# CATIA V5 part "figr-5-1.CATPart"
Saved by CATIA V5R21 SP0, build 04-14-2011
Part number: Part1
Bounding box of the stored display mesh (mm): x -23 to 23, y -104 to 104, z 0 to 68
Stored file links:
  D:\CATIA V5R21 E-RESOURCES\CATIA-V5R21\catia-v5r21-prt\c05-catia-v5r20-prt\catia-v5r21-figr-5-1.CATPart
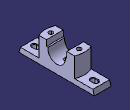
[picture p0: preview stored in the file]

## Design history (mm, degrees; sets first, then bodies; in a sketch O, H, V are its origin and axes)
Sketch1 on yz-plane, origin (0, 0, 0), H (0, 1, 0), V (0, 0, 1)
  line L1 (0, 0) -> (104, 0)
  point P1 (104, 0)
  line L2 (104, 0) -> (100, 14)
  point P2 (100, 14)
  line L3 (100, 14) -> (54, 14)
  point P3 (54, 14)
  line L4 (54, 14) -> (54, 68)
  point P4 (54, 68)
  line L5 (54, 68) -> (28, 68)
  point P5 (28, 68)
  line L6 (28, 68) -> (28, 52)
  point P6 (28, 52)
  line L7 (28, 52) -> (23.6643, 52)
  axis line L8 (0, 0) -> (0, 150)
  point P8 (0, 0)
  construction line L9 through (0, 0) direction (-1, 0)
  construction line L10 through (0, 0) direction (0, 1)
  point P13 (-104, 0)
  point P14 (-100, 14)
  point P15 (-54, 14)
  point P16 (-54, 68)
  point P17 (-28, 68)
  point P18 (-28, 52)
  line L11 (0, 0) -> (-104, 0)
  line L12 (-104, 0) -> (-100, 14)
  line L13 (-100, 14) -> (-54, 14)
  line L14 (-54, 14) -> (-54, 68)
  line L15 (-54, 68) -> (-28, 68)
  line L16 (-28, 68) -> (-28, 52)
  line L17 (-28, 52) -> (-23.6643, 52)
  arc A1 centre (0, 48) radius 24 from (-23.6643, 52) to (23.6643, 52) ccw
  point P19 (0, 48)
  point P20 (13.2665, 68)
  distance P1 P13 = 208
  length L2 V = 14
  length L2 H = 4
  distance L4 L14 = 108
  distance L16 L6 = 56
  distance L1 L5 = 68
  length L6 = 16
  distance P19 L7 = 4
  radius A1 = 24
  horizontal: L1 H, L3 H, L5 H, L7 H
  vertical: L4 V, L6 V, L8 V
  symmetry: O P8 L8, H L9 L8, V L10 L8, P1 P13 L8, P2 P14 L8, P3 P15 L8, P4 P16 L8, P5 P17 L8, P6 P18 L8, L1 L11 L8, L2 L12 L8, L3 L13 L8, L4 L14 L8, L5 L15 L8, L6 L16 L8, L7 L17 L8
  coincidence: P19 L8, A1 P20, P20 L5, O P8
Pad1: profile Sketch1, direction (1, 0, 0), length 23, mirrored extent
Body1 (main body)
  Sketch2 on face of Pad1, origin (0, 0, 68), H (1, 0, 0), V (0, 1, 0)
    arc A1 centre (0, 0) radius 54 from (-23, 48.8569) to (23, 48.8569) cw
    point P1 (0, 0)
    point P2 (-23, 48.8569)
    point P3 (23, 48.8569)
    reference projected line E1 (23, 54) -> (23, 28) from edge [face of Pad1 | face of Pad1]
    reference projected line E2 (-23, 54) -> (-23, 28) from edge [face of Pad1 | face of Pad1]
    reference projected line E3 (-23, 54) -> (23, 54) from edge [face of Pad1 | face of Pad1]
    axis line L1 (-38.3733, 0) -> (57.2772, 0)
    point P4 (-38.3733, 0)
    point P6 (-23, -48.8569)
    point P7 (23, -48.8569)
    arc A2 centre (0, 0) radius 54 from (-23, -48.8569) to (23, -48.8569) ccw
    line L2 (-23, 48.8569) -> (-23, -48.8569)
    point P9 (-23, -48.8569)
    line L3 (23, 48.8569) -> (23, -48.8569)
    coincidence: P3 E1, P2 E2, P1 O, P4 H, P9 P6
    tangency: A1 E3
    horizontal: L1 H
    symmetry: P2 P6 L1, P3 P7 L1, A1 A2 L1
    vertical: L2 V, L3 V
  Pocket1: profile Sketch2, direction (0, 0, -1), up to face of Pad1, outer side
  Sketch3 on face of Pad1, origin (0, 0, 0), H (1, 0, 0), V (0, -1, 0)
    line L1 (-13, 52) -> (13, 52)
    line L2 (13, 52) -> (13, 26)
    line L3 (13, 26) -> (-13, 26)
    line L4 (-13, 26) -> (-13, 52)
    axis line L5 (13, 26) -> (-13, 52)
    point P5 (0, 39)
    length L2 = 26
    length L1 = 26
    distance P5 O H = 0
    distance P5 H = 39
    horizontal: L1 H, L3 H
    vertical: L2 V, L4 V
    midpoint: P5 L5
  Pocket2: profile Sketch3, direction (0, 0, 1), length 10
  Sketch4 on face of Pocket2, origin (0, -39, 10), H (1, 0, 0), V (0, -1, 0)
    point P1 (0, 0)
    reference projected point E1 (0, 0) from vertex of Sketch7
    coincidence: E1 P1
  Hole1: placed by Sketch4, at (0, -39, 10) direction (0, 0, 1), diameter 12, through (limit type 3)
  Sketch5 on face of Pad1, origin (0, 0, 14), H (1, 0, 0), V (0, 1, 0)
    construction line L1 (0, -85) -> (0, -77)
    point P1 (0, -85)
    line L2 (-6, -85) -> (-6, -77)
    line L3 (6, -77) -> (6, -85)
    arc A1 centre (0, -77) radius 6 from (-6, -77) to (6, -77) cw
    arc A2 centre (0, -85) radius 6 from (6, -85) to (-6, -85) cw
    point P7 (0, -81)
    distance A1 A2 = 20
    distance L3 L2 = 12
    distance P7 H = 81
    coincidence: P1 V
    vertical: L1 V
    tangency: A1 L2, A2 L2, A1 L3, A2 L3
    parallelism: L1 L2
    midpoint: P7 L1
  Pocket3: profile Sketch5, direction (0, 0, -1), through (limit type 3)
  Chamfer1: length 1.5, angle 45, on 1 edge
  Sketch6 on yz-plane, origin (0, 0, 0), H (0, 1, 0), V (0, 0, 1)
    axis line L1 (0, 0) -> (0, 35.393)
    reference projected arc E1 centre (0, 48) radius 24 from (-23.6643, 52) to (23.6643, 52) ccw from edge [face of Pad1 | face of Pad1]
    projected arc E2 centre (0, 48) radius 24 from (0, 24) to (4, 24.3357) ccw from edge [face of Pad1 | face of Pad1]
    point P4 (4, 24.3357)
    line L2 (4, 24.3357) -> (4, 16)
    line L3 (4, 16) -> (0, 16)
    point P6 (0, 16)
    line L4 (0, 16) -> (0, 24)
    point P7 (0, 24)
    point P8 (0, 24)
    "Radius" L2 L1 = 4
    distance E1 L3 = 8
    vertical: L1 V, L2 V, L4 V
    coincidence: P4 E1, P6 L1, P7 E1, L1 P8, P7 P8
    horizontal: L3 H
  Groove1: profile Sketch6, axis Sketch6.L1, angle 360
  Mirror1: of Pocket2, Sketch3, Hole1, Pocket3, Sketch5, Chamfer1, about zx-plane
  Sketch7 on face of Pocket2, origin (0, 0, 10), H (1, 0, 0), V (0, -1, 0)
    point P1 (0, 39)
    axis line L1 (13, 26) -> (-13, 52)
    point P2 (13, 26)
    point P3 (-13, 52)
    reference projected point E1 (13, 26) from vertex [face of Pocket2 | face of Pad1 | face of Pocket2]
    reference projected point E2 (-13, 52) from vertex [face of Pocket2 | face of Pad1 | face of Pocket2]
    coincidence: P1 V, L1 P1, E1 P2, P3 E2
    midpoint: P1 L1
